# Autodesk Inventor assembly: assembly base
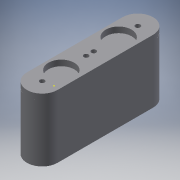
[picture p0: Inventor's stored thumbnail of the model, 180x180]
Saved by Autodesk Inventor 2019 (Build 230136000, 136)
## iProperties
Created: 2020-02
Part Number: assembly base
Document SubType Name: Assembly
Designer: user
Author: user
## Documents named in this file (3)
- F:\assembly base.iam
- F:\BME\drawing bot base.ipt
- F:\db cube.ipt
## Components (2 placed, 2 different names)
1. drawing bot base:1 — Mate:1
2. db cube:1 — Mate:1
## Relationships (1: Mate 1)
- Mate:1: drawing bot base:1 ↔ db cube:1
